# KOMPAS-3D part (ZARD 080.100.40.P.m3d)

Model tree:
1. Плоскость под углом:1
     Угол = -15
2. Булева операция:1
3. Булева операция:2
4. Булева операция:3
5. Булева операция:4
6. Булева операция:5
7. Булева операция:6
8. Булева операция:7
9. Булева операция:8
10. Булева операция:9
11. Булева операция:10
12. Булева операция:11
13. Булева операция:12
14. Булева операция:13
15. Булева операция:14
16. Булева операция:15
17. Булева операция:16
18. Булева операция:17
19. Булева операция:18
20. Булева операция:19
21. Булева операция:20
22. Булева операция:21
23. Булева операция:22
24. Булева операция:23
25. Булева операция:24
26. Булева операция:25
27. Булева операция:26
28. Булева операция:27
29. Булева операция:28
30. Булева операция:29
31. Булева операция:30  (labels: C:\Program Files\ASCON\KOMPAS-3D V13\Sys\GRAPHIC.LYT)

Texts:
  ЗАРД 080.100.40-ХХ.Р
  ООО "ИК Энерпред-Ярдос"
